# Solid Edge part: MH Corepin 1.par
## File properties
Author: davee
Template: MH Die Plate.par
Last saved by: davee
Revision: 18
Application: Solid Edge
Accuracy: 0.990
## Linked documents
MH Die Plate.par
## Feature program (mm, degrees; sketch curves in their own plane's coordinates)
part copy "CopiedPart_1"
sketch for "ExtrudedCutout_1" plane through (19, 100, -15.9375) normal (0, 1, 0) x-axis (-1, 0, 0)
  line (-7.569, 3.474) -> (7.047, 3.474)
extrude "ExtrudedCutout_1" cut finite 10 along -normal
sketch for "ExtrudedProtrusion_1" plane through (19, 100, -16.7005) normal (0, 1, 0) x-axis (-1, 0, 0)
extrude "ExtrudedProtrusion_1" add finite 40 along +normal
sketch for "ExtrudedProtrusion_2" plane through (19, 140, -15.9375) normal (0, 1, 0) x-axis (-1, 0, 0)
extrude "ExtrudedProtrusion_2" add finite 5 along -normal
sketch for "unnamed Cutout 1" plane through (19, 140, -15.9375) normal (0, 1, 0) x-axis (-1, 0, 0)
  line (-11.8512, 6.22) -> (11.736, 6.22)
extrude "unnamed Cutout 1" cut through along -normal
delete faces "unnamed DeleteFaces 1"
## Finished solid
Body 1: solid body, 15 faces, 25 edges, 13 vertices.
  Faces by surface: plane 9, cylinder 5, cone 1
  Edges by curve: line 13, circle 12
Bounding box of the edges (mm): 16.000 x 73.195 x 13.000, from (11, 66.805, -22.7175) to (27, 140, -9.7175).
Cylindrical faces by radius (mm): R1.1165 x1, R1.6747 x1, R2.233 x1, R5 x1, R8 x1
Conical faces (half-angle, radius in mm at the cone's reference point): 59 deg R2.233 x1
Planar faces by outward normal: +y 1, +z 2, -y 5, -z 1
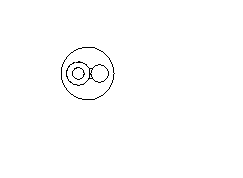
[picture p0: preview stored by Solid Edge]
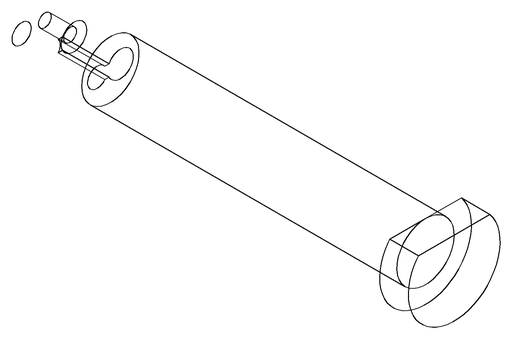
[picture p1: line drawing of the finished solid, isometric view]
